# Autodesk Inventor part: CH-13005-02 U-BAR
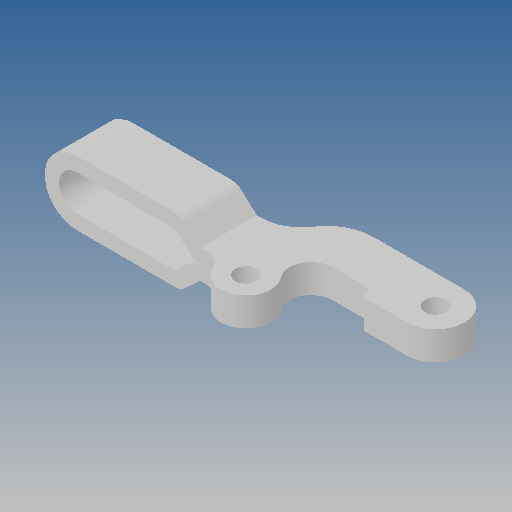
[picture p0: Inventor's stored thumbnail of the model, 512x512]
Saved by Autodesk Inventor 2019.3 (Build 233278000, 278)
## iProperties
Created: 2012-09
Part Number: CH-13005-02 U-BAR
Material: Ogólny
Document SubType Name: Modeling
Designer: CADENGINEERING4
Density: 1 g/cm^3
Appearance: Domyślna
Author: CADENGINEERING4
Revision Number: ÈÎºÎ
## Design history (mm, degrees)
feature "ÇÐ³ý-À­Éì1"
node "Bryła1"
